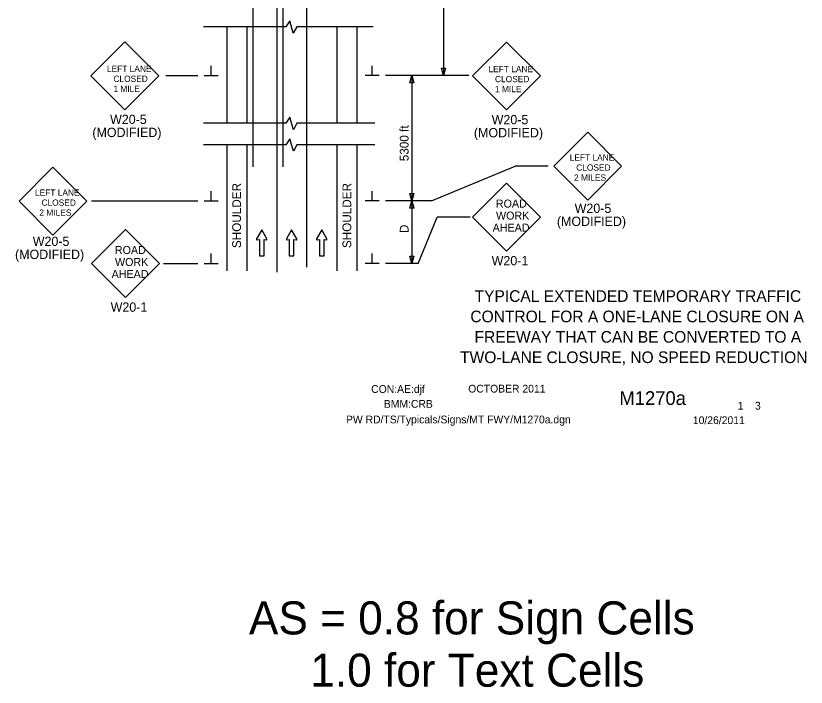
# Model space of a CAD drawing. Extents: x 16794 to 19504, y 7009 to 8243.
# Drawn here: x 16807 to 17439, y 7009 to 7546 of the extents above; entities that cross this region are included whole.
import ezdxf

# ---------------------------------------------------------------- set-up
doc = ezdxf.new("R2010")
doc.units = 0
for name, color, linetype in [('ALI_LEGAL_EX', 7, 'Continuous'), ('BORDER', 7, 'Continuous'), ('BORDER_SIGNAL_WO', 7, 'Continuous'), ('MT_SCRATCH_LEVEL_E', 7, 'Continuous'), ('PAVT_EDGE_EX', 7, 'Continuous'), ('TRAFFIC_SIGNS_PR', 7, 'Continuous'), ('TYPICAL_TEXT_DIMEN_PR', 7, 'Continuous')]:
    doc.layers.add(name, color=color, linetype=linetype)

msp = doc.modelspace()

# ---------------------------------------------------------------- linework, layer by layer
at = {"layer": 'ALI_LEGAL_EX'}
for p, q in [((16995.95, 8243.16), (16995.95, 7425.02)), ((17019.95, 8243.16), (17019.95, 7425.02))]:
    msp.add_line(p, q, dxfattribs=at)
for points in [[(17015.15, 7513.09), (17015.15, 7488.09)], [(17039.15, 7488.09), (17039.15, 7513.09)], [(17015.15, 7408.55), (17015.15, 7380.48)], [(17039.15, 7380.48), (17039.15, 7408.55)]]:
    msp.add_lwpolyline(points, dxfattribs=at)
at = {"layer": 'MT_SCRATCH_LEVEL_E'}
for p, q in [((17003.15, 7374.59), (16999.04, 7367.35)), ((17007.3, 7367.35), (17003.15, 7374.59)), ((17027.06, 7374.59), (17022.94, 7367.35)), ((17031.2, 7367.35), (17027.06, 7374.59)), ((17051.11, 7374.59), (17047, 7367.35)), ((17055.26, 7367.35), (17051.11, 7374.59)), ((16999.52, 7366.67), (17001.3, 7366.98)), ((17001.3, 7366.98), (17001.3, 7353.73)), ((17005.04, 7353.73), (17005.04, 7366.98)), ((17005.04, 7366.98), (17006.82, 7366.67)), ((17023.43, 7366.67), (17025.2, 7366.98)), ((17025.2, 7366.98), (17025.2, 7353.73)), ((17028.95, 7353.73), (17028.95, 7366.98)), ((17028.95, 7366.98), (17030.72, 7366.67)), ((17047.48, 7366.67), (17049.26, 7366.98)), ((17049.26, 7366.98), (17049.26, 7353.73)), ((17053, 7353.73), (17053, 7366.98)), ((17053, 7366.98), (17054.78, 7366.67)), ((17001.3, 7353.73), (17005.04, 7353.73)), ((17025.2, 7353.73), (17028.95, 7353.73)), ((17049.26, 7353.73), (17053, 7353.73))]:
    msp.add_line(p, q, dxfattribs=at)
for centre, start, end in [((16999.45, 7367.13), 150.42484, 279.96381), ((17006.89, 7367.13), 260.03619, 29.77312), ((17023.35, 7367.13), 150.42484, 279.96381), ((17030.79, 7367.13), 260.03619, 29.77312), ((17047.41, 7367.13), 150.42484, 279.96381), ((17054.85, 7367.13), 260.03619, 29.77312)]:
    msp.add_arc(centre, 0.463, start, end, dxfattribs=at)
at = {"layer": 'PAVT_EDGE_EX'}
for p, q in [((17015.15, 8169.87), (17015.15, 7340.69)), ((17039.15, 7344.87), (17039.15, 8169.87)), ((16975.15, 7536.9), (16975.15, 7459.76)), ((16991.15, 7536.9), (16991.15, 7459.74)), ((17063.15, 7536.91), (17063.15, 7459.76)), ((17079.15, 7536.91), (17079.15, 7459.76)), ((16975.15, 7442.61), (16975.15, 7341.8)), ((16991.15, 7442.61), (16991.15, 7341.8)), ((17063.15, 7442.61), (17063.15, 7341.8)), ((17079.15, 7442.61), (17079.15, 7341.8))]:
    msp.add_line(p, q, dxfattribs=at)
at = {"layer": 'TRAFFIC_SIGNS_PR'}
for p, q in [((16893.72, 7524.91), (16866.57, 7497.76)), ((16920.88, 7497.76), (16893.72, 7524.91)), ((17198.86, 7524.68), (17171.71, 7497.53)), ((17226.02, 7497.53), (17198.86, 7524.68)), ((16866.57, 7497.76), (16893.72, 7470.6)), ((16893.72, 7470.6), (16920.88, 7497.76)), ((17171.71, 7497.53), (17198.86, 7470.38)), ((17198.86, 7470.38), (17226.02, 7497.53)), ((17263.82, 7452.69), (17236.67, 7425.54)), ((17290.97, 7425.54), (17263.82, 7452.69)), ((16836.23, 7424.66), (16809.07, 7397.51)), ((16863.38, 7397.51), (16836.23, 7424.66)), ((17236.67, 7425.54), (17263.82, 7398.39)), ((17263.82, 7398.39), (17290.97, 7425.54)), ((17198.86, 7411.97), (17171.7, 7384.82)), ((17226.01, 7384.82), (17198.86, 7411.97)), ((16809.07, 7397.51), (16836.23, 7370.35)), ((16836.23, 7370.35), (16863.38, 7397.51)), ((17171.7, 7384.82), (17198.86, 7357.67)), ((17198.86, 7357.67), (17226.01, 7384.82)), ((16894.19, 7374.9), (16867.03, 7347.74)), ((16921.34, 7347.74), (16894.19, 7374.9)), ((16867.03, 7347.74), (16894.19, 7320.59)), ((16894.19, 7320.59), (16921.34, 7347.74))]:
    msp.add_line(p, q, dxfattribs=at)
at = {"layer": 'TYPICAL_TEXT_DIMEN_PR'}
for p, q in [((17148.59, 7847.81), (17148.59, 7497.81)), ((17025.67, 7541.7), (17022.41, 7536.9)), ((17028.41, 7531.76), (17025.67, 7541.7)), ((17022.41, 7536.9), (16956.47, 7536.9)), ((17031.15, 7536.9), (17028.41, 7531.76)), ((17092.32, 7536.9), (17031.15, 7536.9)), ((16962.78, 7497.81), (16962.78, 7505.59)), ((17091.53, 7497.81), (17091.53, 7505.59)), ((17148.59, 7497.81), (17147.02, 7503.67)), ((17147.02, 7503.67), (17148.59, 7503.67)), ((17148.59, 7503.67), (17150.16, 7503.67)), ((17150.16, 7503.67), (17148.59, 7497.81)), ((16926.41, 7497.81), (16952.15, 7497.81)), ((16957.15, 7497.81), (16968.4, 7497.81)), ((17097.15, 7497.81), (17085.9, 7497.81)), ((17168.73, 7497.81), (17102.15, 7497.81)), ((17121.58, 7491.94), (17123.15, 7497.81)), ((17123.15, 7497.81), (17123.15, 7397.81)), ((17123.15, 7497.81), (17124.72, 7491.94)), ((17123.15, 7491.94), (17121.58, 7491.94)), ((17124.72, 7491.94), (17123.15, 7491.94)), ((17025.76, 7464.54), (17022.5, 7459.74)), ((17028.5, 7454.6), (17025.76, 7464.54)), ((17022.5, 7459.74), (16956.56, 7459.74)), ((17031.24, 7459.74), (17028.5, 7454.6)), ((17093.57, 7459.74), (17031.24, 7459.74)), ((17025.76, 7447.41), (17022.5, 7442.61)), ((17028.5, 7437.47), (17025.76, 7447.41)), ((17022.5, 7442.61), (16956.56, 7442.61)), ((17031.24, 7442.61), (17028.5, 7437.47)), ((17093.57, 7442.61), (17031.24, 7442.61)), ((17138.8, 7397.81), (17205.78, 7425.54)), ((17232.27, 7425.54), (17205.78, 7425.54)), ((16962.78, 7397.81), (16962.78, 7405.59)), ((17091.53, 7397.81), (17091.53, 7405.59)), ((17123.15, 7397.81), (17121.58, 7403.67)), ((17121.58, 7403.67), (17123.15, 7403.67)), ((17123.15, 7403.67), (17124.72, 7403.67)), ((17124.72, 7403.67), (17123.15, 7397.81)), ((16867, 7397.81), (16952.15, 7397.81)), ((16957.15, 7397.81), (16968.4, 7397.81)), ((17097.15, 7397.81), (17085.9, 7397.81)), ((17138.8, 7397.81), (17102.15, 7397.81)), ((17121.58, 7391.94), (17123.15, 7397.81)), ((17123.15, 7397.81), (17123.15, 7347.81)), ((17123.15, 7397.81), (17124.72, 7391.94)), ((17123.15, 7391.94), (17121.58, 7391.94)), ((17124.72, 7391.94), (17123.15, 7391.94)), ((17128.15, 7347.81), (17143.36, 7384.82)), ((17169.85, 7384.82), (17143.36, 7384.82)), ((16962.78, 7347.81), (16962.78, 7355.59)), ((17091.53, 7347.81), (17091.53, 7355.59)), ((17123.15, 7347.81), (17121.58, 7353.67)), ((17121.58, 7353.67), (17123.15, 7353.67)), ((17123.15, 7353.67), (17124.72, 7353.67)), ((17124.72, 7353.67), (17123.15, 7347.81)), ((16924.65, 7347.81), (16952.15, 7347.81)), ((16957.15, 7347.81), (16968.4, 7347.81)), ((17097.15, 7347.81), (17085.9, 7347.81)), ((17128.15, 7347.81), (17102.15, 7347.81))]:
    msp.add_line(p, q, dxfattribs=at)

# ---------------------------------------------------------------- texts
at = {"layer": 'BORDER'}
for s, p in [('TYPICAL EXTENDED TEMPORARY TRAFFIC', (17173.38, 7317.03)), ('CONTROL FOR A ONE-LANE CLOSURE ON A', (17170, 7300.73)), ('FREEWAY THAT CAN BE CONVERTED TO A', (17173.33, 7284.43)), ('TWO-LANE CLOSURE, NO SPEED REDUCTION ', (17161.79, 7268.13))]:
    msp.add_text(s, height=9.3, dxfattribs=at).set_placement(p)
at = {"layer": 'BORDER_SIGNAL_WO'}
for s, height, p in [('CON:AE:djf  ', 6.2, (17090.69, 7244.31)), ('    OCTOBER 2011    ', 6.2, (17159.08, 7244.59)), ('    M1270a   ', 11, (17272.86, 7234.63)), ('BMM:CRB   ', 6.2, (17100.81, 7232.42)), (' 1    3 ', 6.2, (17381.45, 7230.95)), ('PW RD/TS/Typicals/Signs/MT FWY/M1270a.dgn      ', 6.2, (17070.55, 7219.96)), ('10/26/2011    ', 6.2, (17347.93, 7219.38)), ('AS = 0.8 for Sign Cells', 26.4241, (16992.91, 7051.3)), ('     1.0 for Text Cells', 26.4241, (16992.91, 7009.52))]:
    msp.add_text(s, height=height, dxfattribs=at).set_placement(p)
at = {"layer": 'TRAFFIC_SIGNS_PR'}
for s, height, p in [('LEFT LANE', 5, (16879.35, 7500.8)), ('LEFT LANE', 5, (17184.49, 7500.58)), ('CLOSED', 5, (16884.56, 7492.8)), ('CLOSED', 5, (17189.7, 7492.58)), ('1 MILE', 5, (16884.55, 7484.8)), ('1 MILE', 5, (17189.69, 7484.58)), ('W20-5', 7.44, (16881.9, 7459.16)), ('W20-5', 7.44, (17187.04, 7458.94)), ('(MODIFIED)', 7.44, (16867.72, 7448.72)), ('(MODIFIED)', 7.44, (17172.86, 7448.5)), ('LEFT LANE', 5, (17249.45, 7429.87)), ('CLOSED', 5, (17254.66, 7421.87)), ('2 MILES', 5, (17252.91, 7413.87)), ('LEFT LANE', 5, (16821.85, 7401.83)), ('CLOSED', 5, (16827.06, 7393.84)), ('ROAD', 6.4, (17190.4, 7392.36)), ('W20-5', 7.44, (17253.4, 7388.12)), ('2 MILES', 5, (16825.31, 7385.84)), ('WORK', 6.4, (17190.51, 7382.76)), ('(MODIFIED)', 7.44, (17239.22, 7377.68)), ('AHEAD', 6.4, (17187.82, 7373.16)), ('W20-5', 7.44, (16820.07, 7361.72)), ('(MODIFIED)', 7.44, (16805.89, 7351.28)), ('ROAD', 6.4, (16885.73, 7355.28)), ('WORK', 6.4, (16885.84, 7345.68)), ('W20-1', 7.44, (17187.03, 7346.23)), ('AHEAD', 6.4, (16883.15, 7336.08)), ('W20-1', 7.44, (16882.35, 7309.15))]:
    msp.add_text(s, height=height, dxfattribs=at).set_placement(p)
at = {"layer": 'TYPICAL_TEXT_DIMEN_PR'}
for s, p in [('5300 ft', (17120.59, 7429.41)), ('SHOULDER', (16986.57, 7360.01)), ('SHOULDER', (17074.77, 7360.01)), ('D', (17120.59, 7372.02))]:
    msp.add_text(s, height=7, rotation=90, dxfattribs=at).set_placement(p)

doc.saveas('drawing.dxf')
